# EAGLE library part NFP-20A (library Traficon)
90° pinheader for connection to high density (0.025") flatcable connectors
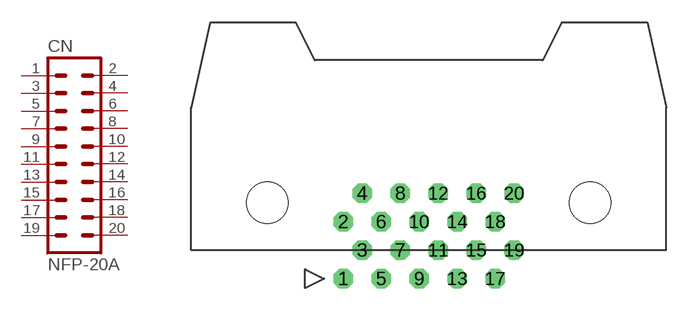
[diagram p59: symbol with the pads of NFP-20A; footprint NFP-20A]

Designator prefix CN

## NFP-20A  [NFP-20A]
1  1  pas
2  2  pas
3  3  pas
4  4  pas
5  5  pas
6  6  pas
7  7  pas
8  8  pas
9  9  pas
10  10  pas
11  11  pas
12  12  pas
13  13  pas
14  14  pas
15  15  pas
16  16  pas
17  17  pas
18  18  pas
19  19  pas
20  20  pas

## Footprint NFP-20A (pad centres in mm)
drill 0.8 octagon: 1 -6.35,-7.62; 2 -6.35,-3.81; 3 -5.08,-5.715; 4 -5.08,-1.905; 5 -3.81,-7.62; 6 -3.81,-3.81; 7 -2.54,-5.715; 8 -2.54,-1.905; 9 -1.27,-7.62; 10 -1.27,-3.81; 11 0,-5.715; 12 0,-1.905; 13 1.27,-7.62; 14 1.27,-3.81; 15 2.54,-5.715; 16 2.54,-1.905; 17 3.81,-7.62; 18 3.81,-3.81; 19 5.08,-5.715; 20 5.08,-1.905
hole 2.8 at -11.43,-2.54
hole 2.8 at 10.16,-2.54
